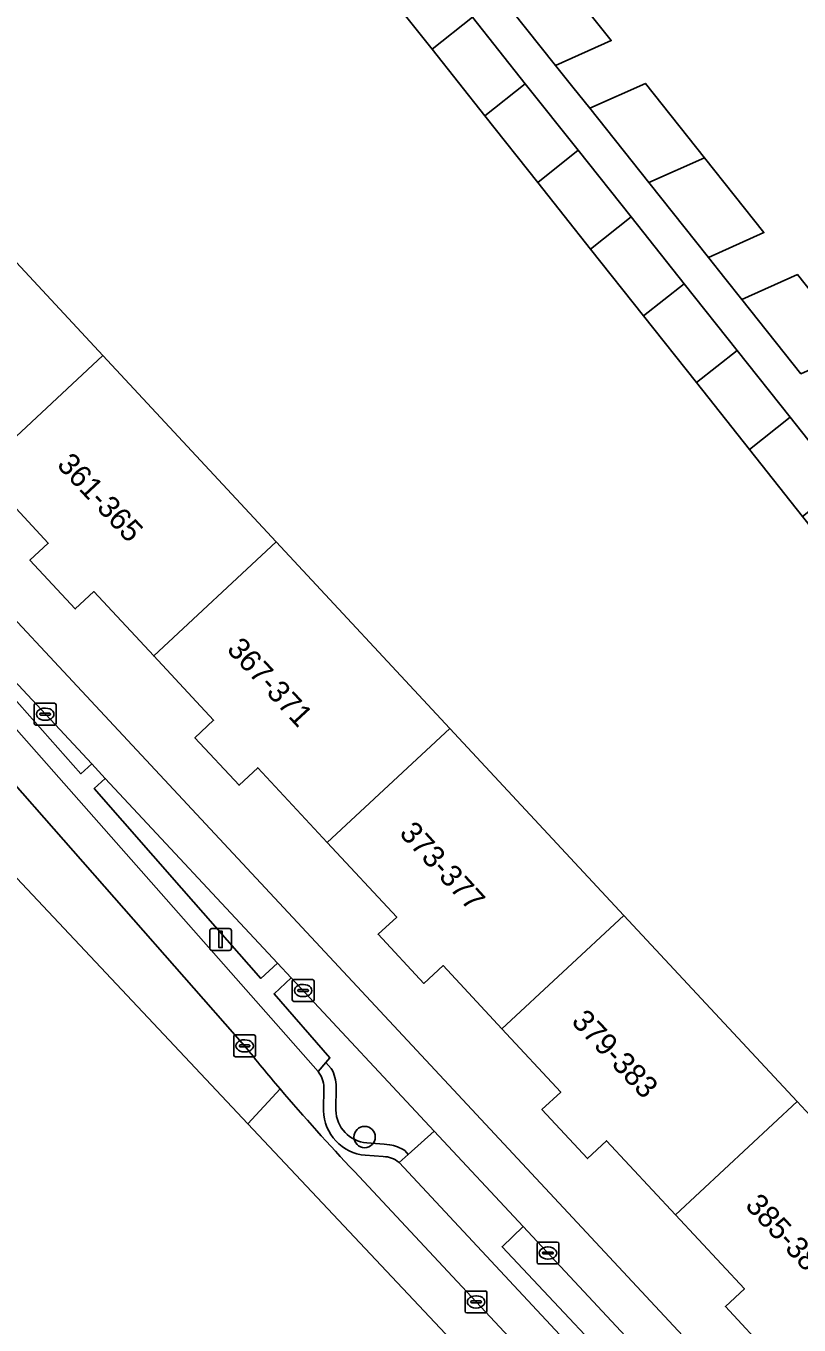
# Model space of a CAD drawing. Extents: x 163147 to 163550, y 380933 to 381639.
# Drawn here: x 163214.1 to 163249.5, y 381137.9 to 381197.5 of the extents above; entities that cross this region are included whole.
import ezdxf

# ---------------------------------------------------------------- set-up
doc = ezdxf.new("R2010")
doc.units = 0
for name, color, linetype in [('IMGEO_Berm_groen', 7, 'Continuous'), ('IMGEO_Berm_open', 7, 'Continuous'), ('IMGEO_Boom', 7, 'Continuous'), ('IMGEO_Erf', 7, 'Continuous'), ('IMGEO_Fietspad_gesloten', 7, 'Continuous'), ('IMGEO_Kolk', 7, 'Continuous'), ('IMGEO_Lichtmast', 7, 'Continuous'), ('IMGEO_Pand', 7, 'Continuous'), ('IMGEO_Pand_nummerreeks', 7, 'Continuous'), ('IMGEO_Parkeervlak_open', 7, 'Continuous'), ('IMGEO_Rijbaan_lokaal_gesloten', 7, 'Continuous'), ('IMGEO_Voetpad_open', 7, 'Continuous')]:
    doc.layers.add(name, color=color, linetype=linetype)

msp = doc.modelspace()

# ---------------------------------------------------------------- linework, layer by layer
at = {"layer": 'IMGEO_Berm_groen'}
for points in [[(163211.002, 381168.987), (163211.372, 381168.554), (163211.631, 381168.775), (163216.584, 381163.212), (163217.075, 381163.662), (163208.015, 381173.372)], [(163226.222, 381153.861), (163225.441, 381153.121), (163228.001, 381150.189), (163227.816, 381149.975), (163228.062, 381149.698)], [(163231.435, 381145.931), (163231.587, 381145.758), (163232.791, 381146.822), (163226.222, 381153.861)], [(163228.294, 381148.851), (163228.273, 381147.788)], [(163229.696, 381146.283), (163230.493, 381146.225), (163230.743, 381146.201)]]:
    msp.add_lwpolyline(points, dxfattribs=at)
for points in [[(163217.693, 381163), (163217.189, 381162.537), (163221.196, 381157.962), (163224.835, 381153.828), (163225.596, 381154.531)], [(163236.873, 381142.447), (163235.896, 381141.52), (163242.768, 381134.219), (163243.701, 381135.131)]]:
    msp.add_lwpolyline(points, close=True, dxfattribs=at)
for centre, radius, start, end in [((163226.581, 381148.837), 1.713, 0.46555, 30.17058), ((163229.82, 381147.825), 1.547, 181.38156, 265.41009), ((163230.43, 381144.376), 1.852, 57.11655, 80.25464)]:
    msp.add_arc(centre, radius, start, end, dxfattribs=at)
at = {"layer": 'IMGEO_Berm_open'}
for points in [[(163228.062, 381149.698), (163227.816, 381149.975), (163227.456, 381149.558)], [(163227.723, 381148.83), (163227.702, 381147.762)], [(163228.273, 381147.788), (163228.294, 381148.851)], [(163230.743, 381146.201), (163230.493, 381146.225), (163229.696, 381146.283)], [(163229.626, 381145.717), (163230.445, 381145.657)], [(163231.174, 381145.393), (163231.587, 381145.758), (163231.435, 381145.931)]]:
    msp.add_lwpolyline(points, dxfattribs=at)
for centre, radius, start, end in [((163226.576, 381148.822), 1.147, 0.37808, 39.90377), ((163226.581, 381148.837), 1.713, 0.46555, 30.17058), ((163229.818, 381147.826), 2.117, 181.72062, 264.78699), ((163229.82, 381147.825), 1.547, 181.38156, 265.41009), ((163230.43, 381144.376), 1.852, 57.11655, 80.25464), ((163230.433, 381144.485), 1.172, 50.78124, 89.40407)]:
    msp.add_arc(centre, radius, start, end, dxfattribs=at)
at = {"layer": 'IMGEO_Boom'}
msp.add_circle((163229.592, 381146.554), 0.489, dxfattribs=at)
at = {"layer": 'IMGEO_Erf'}
for points in [[(163238.211, 381200.222), (163240.909, 381196.832), (163238.357, 381195.692), (163239.147, 381194.7), (163239.922, 381193.727), (163242.472, 381194.867), (163245.185, 381191.458), (163247.913, 381188.03), (163245.363, 381186.892), (163246.123, 381185.937), (163246.895, 381184.967), (163249.445, 381186.105), (163252.159, 381182.695)], [(163264.607, 381120.389), (163281.562, 381138.569), (163278.275, 381142.629), (163276.479, 381141.205), (163274.017, 381144.311), (163273.373, 381145.124), (163271.555, 381147.417), (163269.093, 381150.523), (163266.667, 381153.583), (163264.241, 381156.644), (163261.814, 381159.705), (163259.391, 381162.762), (163256.967, 381165.819), (163254.544, 381168.876), (163252.108, 381171.949), (163249.676, 381175.016), (163247.243, 381178.086), (163244.815, 381181.148), (163242.387, 381184.211), (163239.96, 381187.273), (163237.536, 381190.33), (163235.112, 381193.388), (163232.688, 381196.445), (163230.267, 381199.5)], [(163209.644, 381190.918), (163217.586, 381182.386), (163225.538, 381173.845), (163233.498, 381165.293), (163241.481, 381156.717), (163249.431, 381148.176), (163257.39, 381139.627), (163262.246, 381134.41)]]:
    msp.add_lwpolyline(points, dxfattribs=at)
at = {"layer": 'IMGEO_Fietspad_gesloten'}
for points in [[(163431.634, 380936.983), (163426.381, 380942.59), (163389.734, 380981.756), (163386.168, 380985.564), (163372.648, 381000), (163319.829, 381056.397), (163310.14, 381066.773), (163306.558, 381070.608), (163278.278, 381100.892), (163188.415, 381197.241)], [(163185.896, 381197.102), (163185.926, 381197.07), (163192.218, 381190.305), (163192.37, 381190.141), (163208.015, 381173.372), (163217.075, 381163.662), (163217.693, 381163), (163225.596, 381154.531), (163226.222, 381153.861), (163232.791, 381146.822), (163236.873, 381142.447), (163243.701, 381135.131)]]:
    msp.add_lwpolyline(points, dxfattribs=at)
at = {"layer": 'IMGEO_Kolk'}
for p, q in [((163214.443, 381165.516), (163214.443, 381166.368)), ((163214.518, 381166.442), (163215.37, 381166.442)), ((163214.931, 381166.222), (163214.956, 381166.222)), ((163215.444, 381166.368), (163215.444, 381165.516)), ((163214.702, 381165.936), (163214.702, 381165.948)), ((163215.14, 381165.899), (163214.742, 381165.899)), ((163214.745, 381165.985), (163215.143, 381165.985)), ((163214.954, 381165.662), (163214.929, 381165.662)), ((163215.186, 381165.948), (163215.186, 381165.936)), ((163215.37, 381165.442), (163214.518, 381165.442)), ((163226.273, 381152.845), (163226.273, 381153.697)), ((163226.348, 381153.771), (163227.2, 381153.771)), ((163227.274, 381153.697), (163227.274, 381152.845)), ((163226.532, 381153.265), (163226.532, 381153.277)), ((163226.97, 381153.228), (163226.572, 381153.228)), ((163226.575, 381153.314), (163226.973, 381153.314)), ((163226.761, 381153.551), (163226.786, 381153.551)), ((163227.016, 381153.277), (163227.016, 381153.265)), ((163227.2, 381152.771), (163226.348, 381152.771)), ((163226.784, 381152.991), (163226.759, 381152.991)), ((163223.59, 381150.307), (163223.59, 381151.159)), ((163223.665, 381151.233), (163224.517, 381151.233)), ((163223.849, 381150.727), (163223.849, 381150.739)), ((163223.892, 381150.776), (163224.29, 381150.776)), ((163224.078, 381151.013), (163224.103, 381151.013)), ((163224.333, 381150.739), (163224.333, 381150.727)), ((163224.591, 381151.159), (163224.591, 381150.307)), ((163224.517, 381150.233), (163223.665, 381150.233)), ((163224.287, 381150.69), (163223.889, 381150.69)), ((163224.101, 381150.453), (163224.076, 381150.453)), ((163237.502, 381140.808), (163237.502, 381141.66)), ((163237.577, 381141.734), (163238.429, 381141.734)), ((163237.761, 381141.228), (163237.761, 381141.24)), ((163238.199, 381141.191), (163237.801, 381141.191)), ((163237.804, 381141.277), (163238.202, 381141.277)), ((163237.99, 381141.514), (163238.015, 381141.514)), ((163238.245, 381141.24), (163238.245, 381141.228)), ((163238.503, 381141.66), (163238.503, 381140.808)), ((163238.429, 381140.734), (163237.577, 381140.734)), ((163238.013, 381140.954), (163237.988, 381140.954)), ((163234.206, 381138.567), (163234.206, 381139.419)), ((163234.281, 381139.493), (163235.133, 381139.493)), ((163235.207, 381139.419), (163235.207, 381138.567)), ((163234.465, 381138.987), (163234.465, 381138.999)), ((163234.903, 381138.95), (163234.505, 381138.95)), ((163234.508, 381139.036), (163234.906, 381139.036)), ((163234.694, 381139.273), (163234.719, 381139.273)), ((163234.949, 381138.999), (163234.949, 381138.987)), ((163235.133, 381138.493), (163234.281, 381138.493)), ((163234.717, 381138.713), (163234.692, 381138.713))]:
    msp.add_line(p, q, dxfattribs=at)
for points in [[(163214.443, 381165.516), (163214.443, 381166.368)], [(163214.518, 381166.442), (163215.37, 381166.442)], [(163215.444, 381166.368), (163215.444, 381165.516)], [(163215.37, 381165.442), (163214.518, 381165.442)], [(163226.273, 381152.845), (163226.273, 381153.697)], [(163226.348, 381153.771), (163227.2, 381153.771)], [(163227.274, 381153.697), (163227.274, 381152.845)], [(163227.2, 381152.771), (163226.348, 381152.771)], [(163223.59, 381150.307), (163223.59, 381151.159)], [(163223.665, 381151.233), (163224.517, 381151.233)], [(163224.591, 381151.159), (163224.591, 381150.307)], [(163224.517, 381150.233), (163223.665, 381150.233)], [(163237.502, 381140.808), (163237.502, 381141.66)], [(163237.577, 381141.734), (163238.429, 381141.734)], [(163238.503, 381141.66), (163238.503, 381140.808)], [(163238.429, 381140.734), (163237.577, 381140.734)], [(163234.206, 381138.567), (163234.206, 381139.419)], [(163234.281, 381139.493), (163235.133, 381139.493)], [(163235.207, 381139.419), (163235.207, 381138.567)], [(163235.133, 381138.493), (163234.281, 381138.493)]]:
    msp.add_lwpolyline(points, dxfattribs=at)
for centre, radius, start, end in [((163214.52, 381166.366), 0.0765, 91.55205, 178.44795), ((163214.52, 381166.366), 0.0765, 91.55205, 178.44795), ((163215.368, 381166.366), 0.0765, 1.55205, 88.44795), ((163215.368, 381166.366), 0.0765, 1.55205, 88.44795), ((163214.742, 381165.945), 0.0403, 85.87752, 175.75265), ((163214.739, 381165.935), 0.0366, 178.93798, 274.71019), ((163215.143, 381165.942), 0.043, 264.86636, 352.45326), ((163215.147, 381165.947), 0.0386, 1.73085, 96.63898), ((163214.52, 381165.518), 0.0765, 181.55205, 268.44795), ((163214.52, 381165.518), 0.0765, 181.55205, 268.44795), ((163215.368, 381165.518), 0.0765, 271.55205, 358.44795), ((163215.368, 381165.518), 0.0765, 271.55205, 358.44795), ((163226.35, 381153.695), 0.0765, 91.55205, 178.44795), ((163226.35, 381153.695), 0.0765, 91.55205, 178.44795), ((163227.198, 381153.695), 0.0765, 1.55205, 88.44795), ((163227.198, 381153.695), 0.0765, 1.55205, 88.44795), ((163226.572, 381153.274), 0.0403, 85.87752, 175.75265), ((163226.569, 381153.264), 0.0366, 178.93798, 274.71019), ((163226.973, 381153.271), 0.043, 264.86636, 352.45326), ((163226.977, 381153.276), 0.0386, 1.73085, 96.63898), ((163226.35, 381152.847), 0.0765, 181.55205, 268.44795), ((163226.35, 381152.847), 0.0765, 181.55205, 268.44795), ((163227.198, 381152.847), 0.0765, 271.55205, 358.44795), ((163227.198, 381152.847), 0.0765, 271.55205, 358.44795), ((163223.667, 381151.157), 0.0765, 91.55205, 178.44795), ((163223.667, 381151.157), 0.0765, 91.55205, 178.44795), ((163223.889, 381150.736), 0.0403, 85.87752, 175.75265), ((163223.886, 381150.726), 0.0366, 178.93798, 274.71019), ((163224.29, 381150.733), 0.043, 264.86636, 352.45326), ((163224.294, 381150.738), 0.0386, 1.73085, 96.63898), ((163224.515, 381151.157), 0.0765, 1.55205, 88.44795), ((163224.515, 381151.157), 0.0765, 1.55205, 88.44795), ((163223.667, 381150.309), 0.0765, 181.55205, 268.44795), ((163223.667, 381150.309), 0.0765, 181.55205, 268.44795), ((163224.515, 381150.309), 0.0765, 271.55205, 358.44795), ((163224.515, 381150.309), 0.0765, 271.55205, 358.44795), ((163237.579, 381141.658), 0.0765, 91.55205, 178.44795), ((163237.579, 381141.658), 0.0765, 91.55205, 178.44795), ((163237.801, 381141.237), 0.0403, 85.87752, 175.75265), ((163237.798, 381141.227), 0.0366, 178.93798, 274.71019), ((163238.202, 381141.234), 0.043, 264.86636, 352.45326), ((163238.206, 381141.239), 0.0386, 1.73085, 96.63898), ((163238.427, 381141.658), 0.0765, 1.55205, 88.44795), ((163238.427, 381141.658), 0.0765, 1.55205, 88.44795), ((163237.579, 381140.81), 0.0765, 181.55205, 268.44795), ((163237.579, 381140.81), 0.0765, 181.55205, 268.44795), ((163238.427, 381140.81), 0.0765, 271.55205, 358.44795), ((163238.427, 381140.81), 0.0765, 271.55205, 358.44795), ((163234.283, 381139.417), 0.0765, 91.55205, 178.44795), ((163234.283, 381139.417), 0.0765, 91.55205, 178.44795), ((163235.131, 381139.417), 0.0765, 1.55205, 88.44795), ((163235.131, 381139.417), 0.0765, 1.55205, 88.44795), ((163234.505, 381138.996), 0.0403, 85.87752, 175.75265), ((163234.502, 381138.986), 0.0366, 178.93798, 274.71019), ((163234.906, 381138.993), 0.043, 264.86636, 352.45326), ((163234.91, 381138.998), 0.0386, 1.73085, 96.63898), ((163234.283, 381138.569), 0.0765, 181.55205, 268.44795), ((163234.283, 381138.569), 0.0765, 181.55205, 268.44795), ((163235.131, 381138.569), 0.0765, 271.55205, 358.44795), ((163235.131, 381138.569), 0.0765, 271.55205, 358.44795)]:
    msp.add_arc(centre, radius, start, end, dxfattribs=at)
for centre, major_axis, ratio, start_param, end_param in [((163214.93, 381165.942), (-0.387, 0.002), 0.722429, 4.712389, 7.853982), ((163214.955, 381165.942), (-0.39, 0.002), 0.717154, 1.570796, 4.712389), ((163226.76, 381153.271), (-0.387, 0.002), 0.722429, 4.712389, 7.853982), ((163226.785, 381153.271), (-0.39, 0.002), 0.717154, 1.570796, 4.712389), ((163224.077, 381150.733), (-0.387, 0.002), 0.722429, 4.712389, 7.853982), ((163224.102, 381150.733), (-0.39, 0.002), 0.717154, 1.570796, 4.712389), ((163237.989, 381141.234), (-0.387, 0.002), 0.722429, 4.712389, 7.853982), ((163238.014, 381141.234), (-0.39, 0.002), 0.717154, 1.570796, 4.712389), ((163234.693, 381138.993), (-0.387, 0.002), 0.722429, 4.712389, 7.853982), ((163234.718, 381138.993), (-0.39, 0.002), 0.717154, 1.570796, 4.712389)]:
    msp.add_ellipse(centre, major_axis=major_axis, ratio=ratio, start_param=start_param, end_param=end_param, dxfattribs=at)
at = {"layer": 'IMGEO_Lichtmast'}
for p, q in [((163222.591, 381156.114), (163223.381, 381156.114)), ((163223.381, 381156.114), (163222.591, 381156.114)), ((163222.491, 381155.214), (163222.491, 381156.014)), ((163222.491, 381156.014), (163222.491, 381155.214)), ((163223.481, 381156.014), (163223.481, 381155.214)), ((163223.481, 381155.214), (163223.481, 381156.014)), ((163223.381, 381155.114), (163222.591, 381155.114)), ((163222.591, 381155.114), (163223.381, 381155.114))]:
    msp.add_line(p, q, dxfattribs=at)
msp.add_lwpolyline([(163222.911, 381155.989), (163223.061, 381155.989), (163223.061, 381155.239), (163222.911, 381155.239), (163222.911, 381155.989)], dxfattribs=at)
for centre, start, end in [((163222.591, 381156.014), 90, 180), ((163222.591, 381156.014), 90, 180), ((163223.381, 381156.014), 0, 90), ((163223.381, 381156.014), 360, 90), ((163222.591, 381155.214), 180, 270), ((163222.591, 381155.214), 180, 270), ((163223.381, 381155.214), 270, 0), ((163223.381, 381155.214), 270, 0)]:
    msp.add_arc(centre, 0.1, start, end, dxfattribs=at)
at = {"layer": 'IMGEO_Pand'}
for points in [[(163230.267, 381199.5), (163232.688, 381196.445), (163234.536, 381197.91), (163232.112, 381200.962)], [(163238.211, 381200.222), (163235.659, 381199.082), (163238.357, 381195.692), (163240.909, 381196.832)], [(163235.112, 381193.388), (163236.963, 381194.855), (163234.536, 381197.91), (163232.688, 381196.445)], [(163235.112, 381193.388), (163237.536, 381190.33), (163239.39, 381191.8), (163236.963, 381194.855)], [(163239.922, 381193.727), (163242.635, 381190.319), (163245.185, 381191.458), (163242.472, 381194.867)], [(163239.39, 381191.8), (163237.536, 381190.33), (163239.96, 381187.273), (163241.817, 381188.745)], [(163245.185, 381191.458), (163242.635, 381190.319), (163245.363, 381186.892), (163247.913, 381188.03)], [(163217.586, 381182.386), (163209.644, 381190.918), (163204.028, 381185.69), (163206.745, 381182.771), (163205.876, 381181.962), (163207.975, 381179.707), (163208.829, 381180.501), (163211.955, 381177.143)], [(163242.387, 381184.211), (163244.247, 381185.685), (163241.817, 381188.745), (163239.96, 381187.273)], [(163246.895, 381184.967), (163249.61, 381181.556), (163252.159, 381182.695), (163249.445, 381186.105)], [(163246.678, 381182.625), (163244.247, 381185.685), (163242.387, 381184.211), (163244.815, 381181.148)], [(163217.586, 381182.386), (163211.955, 381177.143), (163215.08, 381173.786), (163214.239, 381173.003), (163216.319, 381170.768), (163217.177, 381171.567), (163219.923, 381168.617), (163225.538, 381173.845)], [(163246.678, 381182.625), (163244.815, 381181.148), (163247.243, 381178.086), (163249.108, 381179.565)], [(163247.243, 381178.086), (163249.676, 381175.016), (163251.545, 381176.497), (163249.108, 381179.565)], [(163227.88, 381160.064), (163233.498, 381165.293), (163225.538, 381173.845), (163219.923, 381168.617), (163222.669, 381165.668), (163221.807, 381164.866), (163223.836, 381162.686), (163224.695, 381163.486)], [(163241.481, 381156.717), (163233.498, 381165.293), (163227.88, 381160.064), (163231.065, 381156.642), (163230.214, 381155.85), (163232.312, 381153.595), (163233.191, 381154.413), (163235.89, 381151.513)], [(163243.854, 381142.984), (163249.431, 381148.176), (163241.481, 381156.717), (163235.89, 381151.513), (163238.59, 381148.613), (163237.729, 381147.811), (163239.819, 381145.566), (163240.693, 381146.38)], [(163243.854, 381142.984), (163247.015, 381139.589), (163246.143, 381138.777), (163248.208, 381136.558), (163249.065, 381137.356), (163251.798, 381134.42), (163257.39, 381139.627), (163249.431, 381148.176)]]:
    msp.add_lwpolyline(points, close=True, dxfattribs=at)
at = {"layer": 'IMGEO_Parkeervlak_open'}
for points in [[(163188.282, 381190.507), (163201.535, 381176.127), (163213.012, 381163.337), (163224.088, 381150.736)], [(163227.456, 381149.558), (163210.979, 381168.218)], [(163227.702, 381147.762), (163227.723, 381148.83)], [(163230.445, 381145.657), (163229.626, 381145.717)], [(163246.127, 381129.352), (163231.174, 381145.393)], [(163229.126, 381144.967), (163257.862, 381114.198)]]:
    msp.add_lwpolyline(points, dxfattribs=at)
for centre, radius, start, end in [((163298.736, 381210.761), 95.788, 218.80325, 220.33112), ((163226.576, 381148.822), 1.147, 0.37808, 39.90377), ((163297.215, 381209.517), 93.823, 220.35279, 223.47151), ((163229.818, 381147.826), 2.117, 181.72062, 264.78699), ((163230.433, 381144.485), 1.172, 50.78124, 89.40407)]:
    msp.add_arc(centre, radius, start, end, dxfattribs=at)
at = {"layer": 'IMGEO_Rijbaan_lokaal_gesloten'}
for points in [[(163224.088, 381150.736), (163213.012, 381163.337), (163201.535, 381176.127), (163188.282, 381190.507), (163186.819, 381192.001), (163186.374, 381192.526), (163182.94, 381196.113), (163180.782, 381193.98), (163202.317, 381170.657), (163205.425, 381167.139), (163224.239, 381147.157)], [(163225.715, 381148.767), (163224.239, 381147.157)], [(163224.239, 381147.157), (163225.715, 381148.767)], [(163224.239, 381147.157), (163352.566, 381010.865)], [(163305.819, 381062.795), (163299.374, 381069.695), (163297.748, 381071.447), (163292.133, 381077.437), (163292.004, 381077.575), (163282.56, 381087.679), (163275.582, 381095.146), (163275.466, 381095.274), (163273.604, 381097.334), (163273.501, 381097.445), (163266.816, 381104.528), (163266.09, 381105.339), (163259.301, 381112.6), (163257.862, 381114.198), (163229.126, 381144.967)]]:
    msp.add_lwpolyline(points, dxfattribs=at)
for centre, radius, start, end in [((163298.736, 381210.761), 95.788, 218.80325, 220.33112), ((163297.215, 381209.517), 93.823, 220.35279, 223.47151)]:
    msp.add_arc(centre, radius, start, end, dxfattribs=at)
at = {"layer": 'IMGEO_Voetpad_open'}
for points in [[(163249.61, 381181.556), (163246.895, 381184.967), (163246.123, 381185.937), (163245.363, 381186.892), (163242.635, 381190.319), (163239.922, 381193.727), (163239.147, 381194.7), (163238.357, 381195.692), (163235.659, 381199.082)], [(163234.536, 381197.91), (163236.963, 381194.855), (163239.39, 381191.8), (163241.817, 381188.745), (163244.247, 381185.685), (163246.678, 381182.625), (163249.108, 381179.565), (163251.545, 381176.497)], [(163188.415, 381197.241), (163278.278, 381100.892), (163306.558, 381070.608)], [(163248.208, 381136.558), (163246.143, 381138.777), (163247.015, 381139.589), (163243.854, 381142.984), (163240.693, 381146.38), (163239.819, 381145.566), (163237.729, 381147.811), (163238.59, 381148.613), (163235.89, 381151.513), (163233.191, 381154.413), (163232.312, 381153.595), (163230.214, 381155.85), (163231.065, 381156.642), (163227.88, 381160.064), (163224.695, 381163.486), (163223.836, 381162.686), (163221.807, 381164.866), (163222.669, 381165.668), (163219.923, 381168.617), (163217.177, 381171.567), (163216.319, 381170.768), (163214.239, 381173.003), (163215.08, 381173.786), (163211.955, 381177.143)]]:
    msp.add_lwpolyline(points, dxfattribs=at)
for points in [[(163211.631, 381168.775), (163211.372, 381168.554), (163210.979, 381168.218), (163227.456, 381149.558), (163227.816, 381149.975), (163228.001, 381150.189), (163225.441, 381153.121), (163226.222, 381153.861), (163225.596, 381154.531), (163224.835, 381153.828), (163221.196, 381157.962), (163217.189, 381162.537), (163217.693, 381163), (163217.075, 381163.662), (163216.584, 381163.212)], [(163236.873, 381142.447), (163232.791, 381146.822), (163231.587, 381145.758), (163231.174, 381145.393), (163246.127, 381129.352), (163246.485, 381129.7), (163246.711, 381129.919), (163243.361, 381133.518), (163244.35, 381134.436), (163243.701, 381135.131), (163242.768, 381134.219), (163235.896, 381141.52)]]:
    msp.add_lwpolyline(points, close=True, dxfattribs=at)

# ---------------------------------------------------------------- texts
at = {"layer": 'IMGEO_Pand_nummerreeks'}
for s, rotation, p in [('361-365', 312.97268, (163215.437, 381177.343)), ('367-371', 312.74936, (163223.23, 381168.883)), ('373-377', 312.48864, (163231.146, 381160.451)), ('379-383', 313.47923, (163239.037, 381151.813)), ('385-389', 312.99045, (163247.007, 381143.379))]:
    msp.add_text(s, height=1, rotation=rotation, dxfattribs=at).set_placement(p)

doc.saveas('drawing.dxf')
